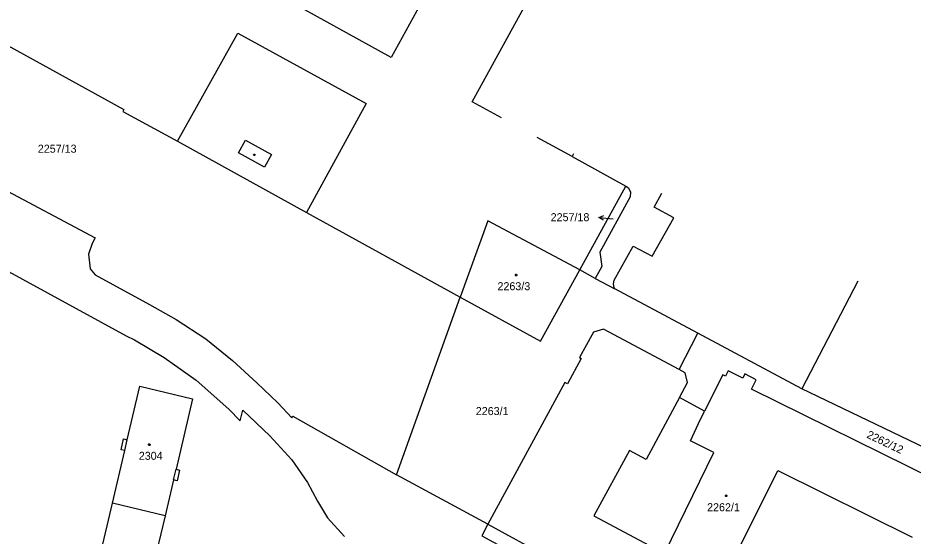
# Model space of a CAD drawing. Extents: x -528274 to -527531, y -1079304 to -1078580.
# Drawn here: x -527864 to -527673.9, y -1079021.9 to -1078911.9 of the extents above; entities that cross this region are included whole.
import ezdxf

# ---------------------------------------------------------------- set-up
doc = ezdxf.new("R2010")
doc.units = 0
doc.layers.add('katastrální mapa', color=7, linetype='Continuous')

msp = doc.modelspace()

# ---------------------------------------------------------------- linework, layer by layer
at = {"layer": 'katastrální mapa'}
for p, q in [((-527765.36, -1078885.09), (-527784.77, -1078920.26)), ((-527767.53, -1078929.65), (-527748.19, -1078894.51)), ((-527784.77, -1078920.26), (-527811.7, -1078905.31)), ((-527874.35, -1078913.18), (-527841.48, -1078931.32)), ((-527830.13, -1078938.05), (-527817.27, -1078915.06)), ((-527817.27, -1078915.06), (-527790.02, -1078930.03)), ((-527790.02, -1078930.03), (-527802.73, -1078953.18)), ((-527761.29, -1078933.08), (-527767.53, -1078929.65)), ((-527899.57, -1078930.98), (-527847.59, -1078958.56)), ((-527841.48, -1078931.32), (-527841.69, -1078931.71)), ((-527841.69, -1078931.71), (-527830.13, -1078938.05)), ((-527817.17, -1078940.48), (-527815.65, -1078937.78)), ((-527815.65, -1078937.78), (-527810.13, -1078940.83)), ((-527746.31, -1078941.3), (-527753.74, -1078937.22)), ((-527830.13, -1078938.05), (-527802.73, -1078953.18)), ((-527811.64, -1078943.55), (-527817.17, -1078940.48)), ((-527810.13, -1078940.83), (-527811.64, -1078943.55)), ((-527746, -1078940.69), (-527746.31, -1078941.3)), ((-527746.31, -1078941.3), (-527734.9, -1078947.57)), ((-527744.71, -1078965.38), (-527734.9, -1078947.57)), ((-527734.9, -1078947.57), (-527734.35, -1078947.92)), ((-527734.35, -1078947.92), (-527733.93, -1078948.89)), ((-527733.93, -1078948.89), (-527733.96, -1078949.88)), ((-527728.86, -1078952.03), (-527727.27, -1078949.1)), ((-527733.96, -1078949.88), (-527740.4, -1078961.59)), ((-527724.72, -1078954.3), (-527728.86, -1078952.03)), ((-527802.73, -1078953.18), (-527770.06, -1078971.14)), ((-527740.61, -1078954.24), (-527737.62, -1078954.51)), ((-527729.34, -1078962.48), (-527724.72, -1078954.3)), ((-527764.23, -1078954.92), (-527770.06, -1078971.14)), ((-527744.71, -1078965.38), (-527764.23, -1078954.92)), ((-527847.59, -1078958.56), (-527848.25, -1078959.75)), ((-527878.12, -1078959.1), (-527840.98, -1078979.38)), ((-527848.25, -1078959.75), (-527849, -1078962.05)), ((-527737.38, -1078967.57), (-527733.37, -1078960.3)), ((-527733.37, -1078960.3), (-527729.34, -1078962.48)), ((-527849, -1078962.05), (-527848.66, -1078965.15)), ((-527740.4, -1078961.59), (-527740.02, -1078964.64)), ((-527848.66, -1078965.15), (-527847.58, -1078966.38)), ((-527753.04, -1078980.5), (-527744.71, -1078965.38)), ((-527741.39, -1078967.16), (-527744.71, -1078965.38)), ((-527740.02, -1078964.64), (-527741.39, -1078967.16)), ((-527847.58, -1078966.38), (-527836.03, -1078972.73)), ((-527741.39, -1078967.16), (-527737.27, -1078969.36)), ((-527737.53, -1078968.35), (-527737.38, -1078967.57)), ((-527685.67, -1078967.77), (-527697.56, -1078990.64)), ((-527737.38, -1078969.11), (-527737.53, -1078968.35)), ((-527737.27, -1078969.36), (-527737.38, -1078969.11)), ((-527719.61, -1078978.82), (-527737.27, -1078969.36)), ((-527783.6, -1079008.86), (-527770.06, -1078971.14)), ((-527770.06, -1078971.14), (-527753.04, -1078980.5)), ((-527836.03, -1078972.73), (-527830.39, -1078975.87)), ((-527830.39, -1078975.87), (-527824.11, -1078980.02)), ((-527840.98, -1078979.38), (-527839.22, -1078980.19)), ((-527741.8, -1078978.59), (-527744.75, -1078983.99)), ((-527739.62, -1078977.97), (-527741.8, -1078978.59)), ((-527723.56, -1078986.54), (-527739.62, -1078977.97)), ((-527723.56, -1078986.54), (-527719.61, -1078978.82)), ((-527697.56, -1078990.64), (-527719.61, -1078978.82)), ((-527839.22, -1078980.19), (-527832.97, -1078983.97)), ((-527824.11, -1078980.02), (-527818.43, -1078984.58)), ((-527832.97, -1078983.97), (-527826.14, -1078988.78)), ((-527818.43, -1078984.58), (-527813.29, -1078989.33)), ((-527744.41, -1078984.18), (-527747.33, -1078989.56)), ((-527744.75, -1078983.99), (-527744.41, -1078984.18)), ((-527722.33, -1078987.19), (-527723.56, -1078986.54)), ((-527721.8, -1078989.27), (-527722.33, -1078987.19)), ((-527713.2, -1078986.82), (-527713.75, -1078987.92)), ((-527710.07, -1078988.37), (-527713.2, -1078986.82)), ((-527826.14, -1078988.78), (-527819.19, -1078994.95)), ((-527714.29, -1078987.65), (-527718.18, -1078995.34)), ((-527713.75, -1078987.92), (-527714.29, -1078987.65)), ((-527709.62, -1078987.45), (-527710.07, -1078988.37)), ((-527707.23, -1078988.71), (-527709.62, -1078987.45)), ((-527708.2, -1078990.67), (-527707.23, -1078988.71)), ((-527840.77, -1079001.43), (-527838.1, -1078990.04)), ((-527838.1, -1078990.04), (-527826.9, -1078992.72)), ((-527813.29, -1078989.33), (-527808.78, -1078993.58)), ((-527747.89, -1078989.3), (-527764.2, -1079019.38)), ((-527747.33, -1078989.56), (-527747.89, -1078989.3)), ((-527723.54, -1078992.48), (-527721.8, -1078989.27)), ((-527654, -1079017.49), (-527708.2, -1078990.67)), ((-527651.89, -1079012.5), (-527697.56, -1078990.64)), ((-527826.9, -1078992.72), (-527830.41, -1079007.68)), ((-527723.54, -1078992.48), (-527730.62, -1079005.62)), ((-527718.18, -1078995.34), (-527723.54, -1078992.48)), ((-527808.78, -1078993.58), (-527805.8, -1078996.78)), ((-527819.19, -1078994.95), (-527816.79, -1078997.38)), ((-527816.79, -1078997.38), (-527816.23, -1078995.13)), ((-527816.23, -1078995.13), (-527810.48, -1079000.6)), ((-527805.8, -1078996.78), (-527805.58, -1078996.45)), ((-527805.58, -1078996.45), (-527783.6, -1079008.86)), ((-527842.07, -1079003.56), (-527841.57, -1079001.24)), ((-527841.57, -1079001.24), (-527840.77, -1079001.43)), ((-527841.3, -1079003.74), (-527840.77, -1079001.43)), ((-527810.48, -1079000.6), (-527805.85, -1079005.71)), ((-527716.22, -1079004.12), (-527721.17, -1079001.64)), ((-527843.91, -1079014.87), (-527841.3, -1079003.74)), ((-527841.3, -1079003.74), (-527842.07, -1079003.56)), ((-527734.16, -1079003.68), (-527741.73, -1079017.56)), ((-527730.62, -1079005.62), (-527734.16, -1079003.68)), ((-527726.73, -1079025.62), (-527716.22, -1079004.12)), ((-527805.85, -1079005.71), (-527802.5, -1079010.54)), ((-527830.95, -1079009.96), (-527830.41, -1079007.68)), ((-527830.41, -1079007.68), (-527829.65, -1079007.86)), ((-527829.65, -1079007.86), (-527830.18, -1079010.14)), ((-527714.53, -1079031.8), (-527702.6, -1079007.97)), ((-527702.6, -1079007.97), (-527674.09, -1079022.13)), ((-527830.95, -1079009.96), (-527832.74, -1079017.6)), ((-527830.18, -1079010.14), (-527830.95, -1079009.96)), ((-527764.2, -1079019.38), (-527783.6, -1079008.86)), ((-527802.5, -1079010.54), (-527800.4, -1079014.48)), ((-527846.51, -1079026.01), (-527843.91, -1079014.87)), ((-527832.74, -1079017.6), (-527843.91, -1079014.87)), ((-527800.4, -1079014.48), (-527798.28, -1079017.99)), ((-527832.74, -1079017.6), (-527834.54, -1079025.25)), ((-527741.73, -1079017.56), (-527726.73, -1079025.62)), ((-527798.28, -1079017.99), (-527794.63, -1079021.97)), ((-527764.2, -1079019.38), (-527765.52, -1079021.81)), ((-527764.2, -1079019.38), (-527747.63, -1079028.38)), ((-527765.52, -1079021.81), (-527748.93, -1079030.76))]:
    msp.add_line(p, q, dxfattribs=at)
for points in [[(-527813.7, -1078940.78), (-527813.61, -1078940.93), (-527813.7, -1078941.08), (-527813.88, -1078941.08), (-527813.97, -1078940.93), (-527813.88, -1078940.78)], [(-527758.19, -1078966.28), (-527758.09, -1078966.3), (-527758.04, -1078966.39), (-527758.02, -1078966.45), (-527758.04, -1078966.54), (-527758.12, -1078966.61), (-527758.19, -1078966.62), (-527758.28, -1078966.59), (-527758.34, -1078966.53), (-527758.36, -1078966.45), (-527758.34, -1078966.36), (-527758.26, -1078966.29)], [(-527836.09, -1079002.3), (-527835.99, -1079002.32), (-527835.94, -1079002.41), (-527835.92, -1079002.47), (-527835.94, -1079002.56), (-527836.02, -1079002.63), (-527836.09, -1079002.64), (-527836.18, -1079002.61), (-527836.24, -1079002.55), (-527836.26, -1079002.47), (-527836.24, -1079002.38), (-527836.16, -1079002.31)], [(-527713.6, -1079013.16), (-527713.5, -1079013.18), (-527713.45, -1079013.27), (-527713.43, -1079013.33), (-527713.45, -1079013.42), (-527713.53, -1079013.49), (-527713.6, -1079013.5), (-527713.69, -1079013.47), (-527713.75, -1079013.41), (-527713.77, -1079013.33), (-527713.75, -1079013.24), (-527713.67, -1079013.17)]]:
    msp.add_lwpolyline(points, close=True, dxfattribs=at)
for points in [[(-527739.66, -1078954.83), (-527740.61, -1078954.24), (-527739.57, -1078953.83)], [(-527721.17, -1079001.64), (-527719.5, -1078997.95), (-527718.18, -1078995.34)]]:
    msp.add_lwpolyline(points, dxfattribs=at)

# ---------------------------------------------------------------- texts
for s, height, p in [('2257/13', 1.7, (-527859.76, -1078940.48)), ('2257/18', 1.7, (-527750.87, -1078955.02)), ('2257/18', 0.1, (-527737.61, -1078954.51)), ('2263/3', 1.7, (-527762.16, -1078969.68)), ('2263/1', 1.7, (-527766.77, -1078996.19)), ('2304', 1.7, (-527838.32, -1079005.69)), ('2262/1', 1.7, (-527717.65, -1079016.61))]:
    msp.add_text(s, height=height, dxfattribs=at).set_placement(p)
msp.add_text('2262/12', height=1.7, rotation=334.4355, dxfattribs=at).set_placement((-527683.92, -1079000.93))

doc.saveas('drawing.dxf')
